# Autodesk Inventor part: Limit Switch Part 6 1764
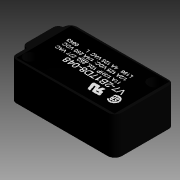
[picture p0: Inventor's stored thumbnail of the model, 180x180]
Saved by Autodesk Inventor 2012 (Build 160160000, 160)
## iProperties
Shininess: 0.0
Created: 2002-01
Part Number: Limit Switch Part 6 1764
Document SubType Name: Modeling
Density: 1 g/cm^3
Material: Default
Density: 0.0
Volumn: 0.0
Area: 0.0
PropertySet Name: Model Information
Control State: 0
Master: False
Checked Out: False
Author: Administrator
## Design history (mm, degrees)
node "Base1"
sketch "Sketch3"
  geometry: L1 (25.274, -15.222)-(-1.011, -15.36); L2 (-1.011, -15.36)-(-1.089, -0.521); L3 (-1.089, -0.521)-(25.196, -0.383); L4 (25.196, -0.383)-(25.274, -15.222)
  constraints: 2 other
feature "Decal1" sketch "Sketch3"
node "Image2"
